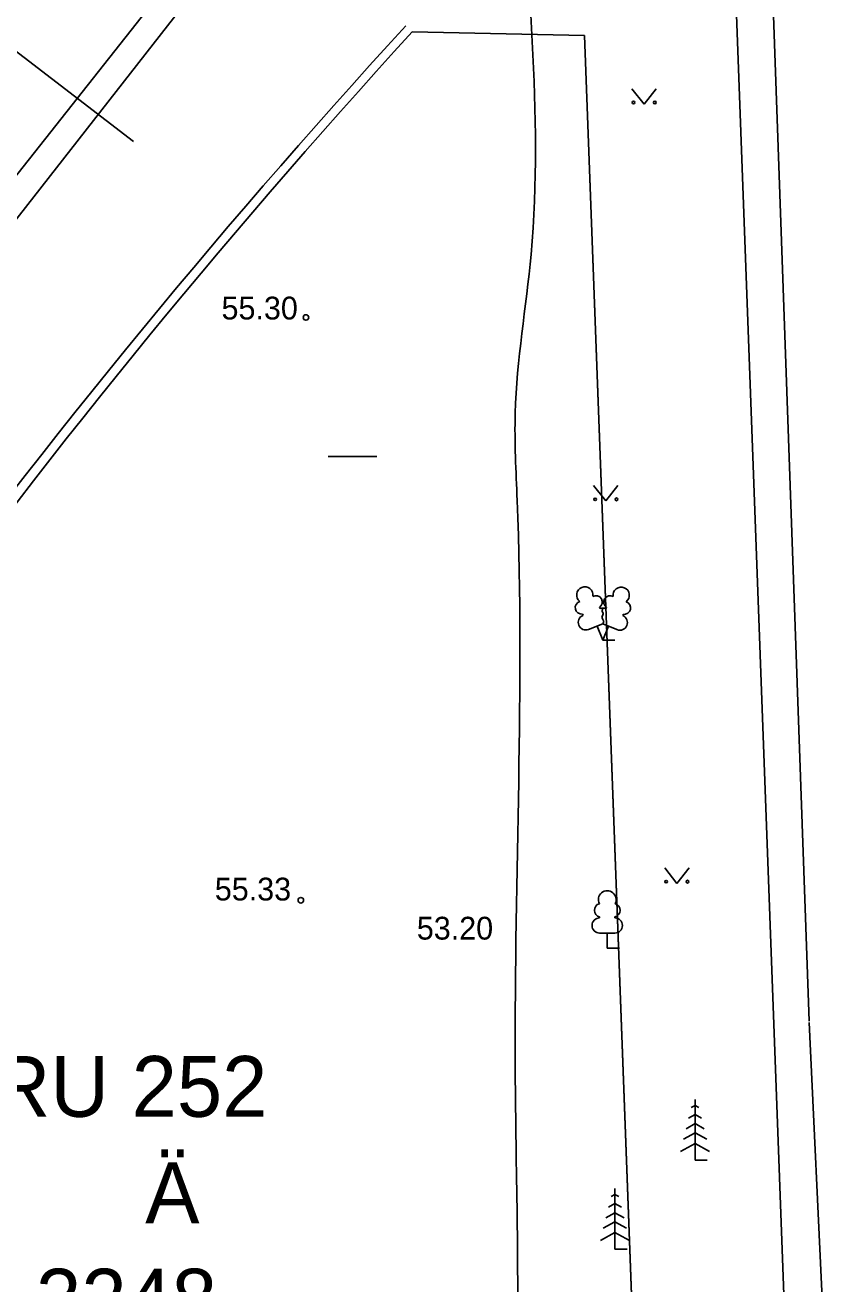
# Model space of a CAD drawing. Extents: x 9156 to 9809, y 2728 to 4000.
# Drawn here: x 9490.03 to 9516.63, y 3522.78 to 3564.19 of the extents above; entities that cross this region are included whole.
import ezdxf

# ---------------------------------------------------------------- set-up
doc = ezdxf.new("R2010")
doc.units = 0
for name, color, linetype in [('Level 11', 7, 'Continuous'), ('Level 12', 7, 'Continuous'), ('Level 17', 7, 'Continuous'), ('Level 18', 7, 'Continuous'), ('Level 5', 7, 'Continuous'), ('Level 54', 7, 'Continuous'), ('Level 56', 7, 'Continuous'), ('Level 6', 7, 'Continuous'), ('Level 7', 7, 'Continuous')]:
    doc.layers.add(name, color=color, linetype=linetype)

msp = doc.modelspace()

# ---------------------------------------------------------------- linework, layer by layer
at = {"layer": 'Level 11'}
for p, q in [((9502.76, 3563.966), (9508.425, 3563.843)), ((9508.425, 3563.843), (9502.76, 3563.966)), ((9508.425, 3563.843), (9510.716, 3502.566)), ((9510.716, 3502.566), (9508.425, 3563.843))]:
    msp.add_line(p, q, dxfattribs=at)
msp.add_arc((9681.939, 3400.237), 242.719, 137.5799, 150.85079, dxfattribs=at)
msp.add_arc((9681.939, 3400.237), 242.719, 137.5799, 150.85079, dxfattribs=at)
at = {"layer": 'Level 12'}
msp.add_line((9473.356, 3575.917), (9493.592, 3560.357), dxfattribs=at)
at = {"layer": 'Level 17'}
for p, q in [((9506.566, 3580.546), (9458.461, 3519.649)), ((9515.816, 3531.421), (9514.498, 3568.474)), ((9515.818, 3531.382), (9517.222, 3501.27))]:
    msp.add_line(p, q, dxfattribs=at)
at = {"layer": 'Level 18'}
msp.add_arc((9265.261, 3707.934), 249.4, 321.41014, 335.20045, dxfattribs=at)
at = {"layer": 'Level 54'}
for p, q in [((9509.989, 3562.091), (9510.392, 3561.586)), ((9510.392, 3561.586), (9510.789, 3562.091)), ((9500, 3550), (9501.593, 3550)), ((9500, 3550), (9501.593, 3550)), ((9508.729, 3549.04), (9509.132, 3548.535)), ((9509.132, 3548.535), (9509.529, 3549.04)), ((9508.939, 3544.995), (9508.922, 3545.035)), ((9509.129, 3544.992), (9509.146, 3545.034)), ((9508.38, 3544.775), (9508.364, 3544.816)), ((9509.684, 3544.765), (9509.701, 3544.805)), ((9508.564, 3544.31), (9509.03, 3544.493)), ((9509.026, 3543.954), (9508.843, 3544.42)), ((9509.026, 3543.954), (9509.216, 3544.417)), ((9509.03, 3544.493), (9509.494, 3544.302)), ((9509.426, 3543.954), (9509.026, 3543.954)), ((9511.066, 3536.462), (9511.469, 3535.957)), ((9511.469, 3535.957), (9511.866, 3536.462)), ((9508.926, 3534.853), (9508.926, 3534.821)), ((9509.426, 3534.853), (9509.426, 3534.821)), ((9509.426, 3534.321), (9508.926, 3534.321)), ((9509.176, 3533.821), (9509.176, 3534.321)), ((9509.576, 3533.821), (9509.176, 3533.821)), ((9512.065, 3528.652), (9511.939, 3528.582)), ((9512.065, 3526.852), (9512.065, 3528.852)), ((9512.065, 3528.652), (9512.191, 3528.582)), ((9512.065, 3528.052), (9511.767, 3527.887)), ((9512.065, 3528.352), (9511.853, 3528.235)), ((9512.065, 3528.352), (9512.277, 3528.235)), ((9512.065, 3528.052), (9512.363, 3527.887)), ((9512.065, 3527.752), (9511.681, 3527.539)), ((9512.065, 3527.752), (9512.449, 3527.539)), ((9512.065, 3527.402), (9511.59, 3527.138)), ((9512.065, 3527.402), (9512.541, 3527.138)), ((9512.465, 3526.852), (9512.065, 3526.852)), ((9509.429, 3525.723), (9509.303, 3525.653)), ((9509.429, 3523.923), (9509.429, 3525.923)), ((9509.429, 3525.723), (9509.555, 3525.653)), ((9509.429, 3525.423), (9509.217, 3525.306)), ((9509.429, 3525.423), (9509.641, 3525.306)), ((9509.429, 3524.823), (9509.045, 3524.61)), ((9509.429, 3525.123), (9509.131, 3524.958)), ((9509.429, 3525.123), (9509.727, 3524.958)), ((9509.429, 3524.823), (9509.813, 3524.61)), ((9509.429, 3524.473), (9508.953, 3524.209)), ((9509.429, 3524.473), (9509.904, 3524.209)), ((9509.829, 3523.923), (9509.429, 3523.923))]:
    msp.add_line(p, q, dxfattribs=at)
msp.add_lwpolyline([(9509.03, 3545.012), (9509.008, 3544.934), (9509.009, 3544.912), (9509.023, 3544.881), (9509.044, 3544.842), (9509.045, 3544.822), (9509.031, 3544.787), (9509.004, 3544.734), (9509.001, 3544.704), (9509.004, 3544.689), (9509.017, 3544.657), (9509.051, 3544.598), (9509.059, 3544.573), (9509.054, 3544.553), (9509.038, 3544.519), (9509.03, 3544.494)], dxfattribs=at)
for centre, radius in [((9510.039, 3561.641), 0.0428), ((9510.739, 3561.641), 0.0452), ((9499.266, 3554.573), 0.0909), ((9508.779, 3548.59), 0.0428), ((9509.479, 3548.59), 0.0452), ((9511.116, 3536.012), 0.0428), ((9511.816, 3536.012), 0.0452), ((9499.099, 3535.401), 0.0909)]:
    msp.add_circle(centre, radius, dxfattribs=at)
for centre, radius, start, end in [((9508.439, 3545.443), 0.269, 111.5027, 232.5173), ((9508.439, 3545.443), 0.269, 350.4856, 111.5002), ((9509.635, 3545.434), 0.269, 67.6168, 188.6314), ((9509.635, 3545.434), 0.269, 306.5997, 67.6143), ((9508.335, 3545.026), 0.212, 106.2979, 277.8684), ((9508.8, 3545.209), 0.212, 305.1345, 116.705), ((9509.271, 3545.205), 0.212, 62.412, 233.9825), ((9509.733, 3545.015), 0.212, 261.2486, 72.8191), ((9508.472, 3544.542), 0.25, 111.5014, 291.5004), ((9509.03, 3544.762), 0.25, 66.7655, 111.5015), ((9509.589, 3544.534), 0.25, 247.6166, 67.6155), ((9509.176, 3535.421), 0.292, 332.5799, 207.4201), ((9508.976, 3535.071), 0.224, 105.2441, 257.079), ((9509.376, 3535.071), 0.224, 282.921, 74.7559), ((9508.926, 3534.571), 0.25, 90, 270), ((9509.426, 3534.571), 0.25, 270, 90)]:
    msp.add_arc(centre, radius, start, end, dxfattribs=at)
msp.add_spline([(9505.952, 3501.106), (9505.952, 3513.373), (9506.213, 3520.529), (9506.148, 3530.055), (9506.214, 3548.556), (9506.149, 3551.427), (9506.67, 3556.647), (9506.41, 3570.729), (9506.412, 3583.875), (9506.217, 3588.181), (9506.543, 3591.574), (9502.174, 3591.966), (9500, 3592.01)], degree=3, dxfattribs=at)
at = {"layer": 'Level 56'}
for p, q in [((9506.566, 3580.546), (9458.461, 3519.649)), ((9515.816, 3531.421), (9514.498, 3568.474)), ((9515.818, 3531.382), (9517.222, 3501.27))]:
    msp.add_line(p, q, dxfattribs=at)
msp.add_arc((9265.261, 3707.934), 249.4, 321.41014, 335.20045, dxfattribs=at)
at = {"layer": 'Level 6'}
msp.add_arc((9681.854, 3399.729), 243.287, 137.47776, 150.74865, dxfattribs=at)
at = {"layer": 'Level 7'}
for p, q in [((9508.911, 3582.331), (9456.401, 3515.151)), ((9515.773, 3501.117), (9512.79, 3581.734))]:
    msp.add_line(p, q, dxfattribs=at)

# ---------------------------------------------------------------- texts
at = {"layer": 'Level 5'}
for s, p in [('VõRU 252', (9485.658, 3528.277)), ('Ä', (9493.981, 3524.777)), ('3248', (9490.393, 3521.277))]:
    msp.add_text(s, height=2, dxfattribs=at).set_placement(p)
at = {"layer": 'Level 54'}
for s, p in [('55.30', (9496.49, 3554.506)), ('55.33', (9496.269, 3535.393)), ('53.20', (9502.913, 3534.107))]:
    msp.add_text(s, height=0.75, dxfattribs=at).set_placement(p)

doc.saveas('drawing.dxf')
